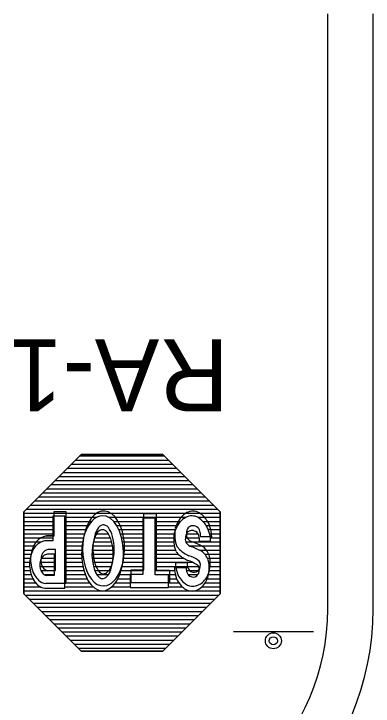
# Model space of a CAD drawing. Extents: x 1806 to 2022, y 110 to 389.
# Drawn here: x 1955.02 to 1964.59, y 293.71 to 312.13 of the extents above; entities that cross this region are included whole.
import ezdxf

# ---------------------------------------------------------------- set-up
doc = ezdxf.new("R2010")
doc.units = 0
for name, color, linetype in [('Level 10', 7, 'Continuous'), ('Level 44', 7, 'Continuous'), ('Level 50', 7, 'Continuous')]:
    doc.layers.add(name, color=color, linetype=linetype)

msp = doc.modelspace()

# ---------------------------------------------------------------- linework, layer by layer
at = {"layer": 'Level 10'}
for p, q in [((1963.38, 296.293), (1963.38, 312.134)), ((1964.59, 296.293), (1964.59, 312.134))]:
    msp.add_line(p, q, dxfattribs=at)
for radius in [7.258, 6.048]:
    msp.add_arc((1957.332, 296.293), radius, 270, 360, dxfattribs=at)
at = {"layer": 'Level 44'}
for p, q in [((1956.813, 300.408), (1955.284, 298.878)), ((1958.991, 300.408), (1956.813, 300.408)), ((1960.52, 298.878), (1958.991, 300.408)), ((1955.284, 298.878), (1955.284, 296.701)), ((1956.092, 298.239), (1956.092, 298.892)), ((1956.092, 298.892), (1956.41, 298.892)), ((1956.41, 298.892), (1956.41, 296.976)), ((1960.52, 296.701), (1960.52, 298.878)), ((1956.381, 298.765), (1956.064, 298.765)), ((1956.064, 298.765), (1956.064, 298.111)), ((1956.381, 296.848), (1956.381, 298.765)), ((1958.786, 298.709), (1958.455, 298.709)), ((1958.455, 298.709), (1958.455, 297.21)), ((1958.482, 298.836), (1958.814, 298.836)), ((1958.482, 297.337), (1958.482, 298.836)), ((1958.786, 297.201), (1958.786, 298.709)), ((1958.814, 298.836), (1958.814, 297.329)), ((1960.198, 298.596), (1960.2, 298.595)), ((1956.064, 298.111), (1955.864, 298.111)), ((1956.092, 298.239), (1955.892, 298.239)), ((1955.901, 298.234), (1956.092, 298.239)), ((1960.293, 298.217), (1959.993, 298.217)), ((1960.267, 298.09), (1959.967, 298.09)), ((1956.104, 297.751), (1955.899, 297.751)), ((1956.104, 297.751), (1955.899, 297.751)), ((1956.13, 297.877), (1955.926, 297.877)), ((1956.13, 297.877), (1955.926, 297.877)), ((1956.104, 297.193), (1956.104, 297.751)), ((1956.104, 297.193), (1956.104, 297.751)), ((1956.13, 297.32), (1956.13, 297.877)), ((1956.13, 297.32), (1956.13, 297.877)), ((1959.296, 297.402), (1959.622, 297.402)), ((1959.322, 297.529), (1959.65, 297.529)), ((1955.895, 297.193), (1956.104, 297.193)), ((1955.895, 297.193), (1956.104, 297.193)), ((1955.922, 297.32), (1956.13, 297.32)), ((1955.922, 297.32), (1956.13, 297.32)), ((1957.441, 297.235), (1957.428, 297.232)), ((1958.455, 297.21), (1958.12, 297.21)), ((1958.12, 297.21), (1958.12, 296.866)), ((1958.146, 296.994), (1958.146, 297.337)), ((1958.146, 297.337), (1958.482, 297.337)), ((1959.139, 297.201), (1958.786, 297.201)), ((1958.814, 297.329), (1959.166, 297.329)), ((1959.139, 296.866), (1959.139, 297.201)), ((1959.166, 297.329), (1959.166, 296.994)), ((1955.847, 296.848), (1956.381, 296.848)), ((1956.41, 296.976), (1955.874, 296.976)), ((1957.428, 296.909), (1957.418, 296.908)), ((1958.12, 296.866), (1959.139, 296.866)), ((1959.166, 296.994), (1958.146, 296.994)), ((1955.284, 296.701), (1956.813, 295.172)), ((1958.991, 295.172), (1960.52, 296.701)), ((1963.003, 295.688), (1960.87, 295.688)), ((1956.813, 295.172), (1958.991, 295.172))]:
    msp.add_line(p, q, dxfattribs=at)
msp.add_lwpolyline([(1955.284, 298.879), (1956.813, 300.408), (1958.991, 300.408), (1960.52, 298.879), (1960.52, 296.701), (1958.991, 295.173), (1956.813, 295.173), (1955.284, 296.701)], close=True, dxfattribs=at)
for points in [[(1959.039, 300.36), (1956.765, 300.36)], [(1959.256, 300.141), (1956.548, 300.141)], [(1959.142, 300.25), (1956.656, 300.25)], [(1959.366, 300.032), (1956.439, 300.032)], [(1959.582, 299.815), (1956.222, 299.815)], [(1959.474, 299.923), (1956.331, 299.923)], [(1959.801, 299.596), (1956.003, 299.596)], [(1959.692, 299.706), (1956.112, 299.706)], [(1959.909, 299.488), (1955.895, 299.488)], [(1960.128, 299.27), (1955.676, 299.27)], [(1960.018, 299.379), (1955.786, 299.379)], [(1960.345, 299.053), (1955.46, 299.053)], [(1960.237, 299.162), (1955.568, 299.162)], [(1960.454, 298.943), (1955.35, 298.943)], [(1960.52, 298.835), (1955.284, 298.835)], [(1956.064, 298.726), (1955.284, 298.726)], [(1957.219, 298.726), (1956.381, 298.726)], [(1959.596, 298.726), (1957.562, 298.726)], [(1960.52, 298.726), (1959.932, 298.726)], [(1956.064, 298.617), (1955.284, 298.617)], [(1956.064, 298.509), (1955.284, 298.509)], [(1957.088, 298.617), (1956.381, 298.617)], [(1957.01, 298.509), (1956.381, 298.509)], [(1958.455, 298.617), (1957.693, 298.617)], [(1958.455, 298.509), (1957.771, 298.509)], [(1959.452, 298.617), (1958.786, 298.617)], [(1959.374, 298.509), (1958.786, 298.509)], [(1960.52, 298.617), (1960.057, 298.617)], [(1960.52, 298.509), (1960.146, 298.509)], [(1956.064, 298.399), (1955.284, 298.399)], [(1956.064, 298.29), (1955.284, 298.29)], [(1956.954, 298.399), (1956.381, 298.399)], [(1956.91, 298.29), (1956.381, 298.29)], [(1957.549, 298.29), (1957.224, 298.29)], [(1958.455, 298.399), (1957.828, 298.399)], [(1958.455, 298.29), (1957.867, 298.29)], [(1959.321, 298.399), (1958.786, 298.399)], [(1959.286, 298.29), (1958.786, 298.29)], [(1959.924, 298.29), (1959.613, 298.29)], [(1960.52, 298.399), (1960.197, 298.399)], [(1960.52, 298.29), (1960.232, 298.29)], [(1956.064, 298.182), (1955.284, 298.182)], [(1956.878, 298.182), (1956.381, 298.182)], [(1957.598, 298.182), (1957.166, 298.182)], [(1958.455, 298.182), (1957.898, 298.182)], [(1959.279, 298.182), (1958.786, 298.182)], [(1959.957, 298.182), (1959.588, 298.182)], [(1960.52, 298.182), (1960.254, 298.182)], [(1955.748, 298.072), (1955.284, 298.072)], [(1955.598, 297.964), (1955.284, 297.964)], [(1956.856, 298.072), (1956.381, 298.072)], [(1956.838, 297.964), (1956.381, 297.964)], [(1957.653, 297.964), (1957.114, 297.964)], [(1957.632, 298.072), (1957.137, 298.072)], [(1958.455, 298.072), (1957.915, 298.072)], [(1958.455, 297.964), (1957.929, 297.964)], [(1959.279, 298.072), (1958.786, 298.072)], [(1959.296, 297.964), (1958.786, 297.964)], [(1960.52, 298.072), (1959.6, 298.072)], [(1960.52, 297.964), (1959.712, 297.964)], [(1955.524, 297.856), (1955.284, 297.856)], [(1955.486, 297.746), (1955.284, 297.746)], [(1956.831, 297.856), (1956.381, 297.856)], [(1956.826, 297.746), (1956.381, 297.746)], [(1957.666, 297.856), (1957.101, 297.856)], [(1957.666, 297.746), (1957.106, 297.746)], [(1958.455, 297.856), (1957.938, 297.856)], [(1958.455, 297.746), (1957.938, 297.746)], [(1959.326, 297.856), (1958.786, 297.856)], [(1959.409, 297.746), (1958.786, 297.746)], [(1960.52, 297.856), (1959.97, 297.856)], [(1960.52, 297.746), (1960.111, 297.746)], [(1955.456, 297.637), (1955.284, 297.637)], [(1956.104, 297.637), (1955.751, 297.637)], [(1956.835, 297.637), (1956.381, 297.637)], [(1957.659, 297.637), (1957.106, 297.637)], [(1958.451, 297.637), (1957.933, 297.637)], [(1959.556, 297.637), (1958.786, 297.637)], [(1960.52, 297.637), (1960.179, 297.637)], [(1955.442, 297.529), (1955.284, 297.529)], [(1955.445, 297.42), (1955.284, 297.42)], [(1956.109, 297.529), (1955.716, 297.529)], [(1956.104, 297.42), (1955.72, 297.42)], [(1956.844, 297.529), (1956.381, 297.529)], [(1956.865, 297.42), (1956.381, 297.42)], [(1957.653, 297.529), (1957.123, 297.529)], [(1957.623, 297.42), (1957.148, 297.42)], [(1958.455, 297.42), (1957.902, 297.42)], [(1958.455, 297.529), (1957.921, 297.529)], [(1959.801, 297.529), (1958.786, 297.529)], [(1959.94, 297.42), (1958.786, 297.42)], [(1960.52, 297.529), (1960.21, 297.529)], [(1960.52, 297.42), (1960.224, 297.42)], [(1955.46, 297.312), (1955.284, 297.312)], [(1955.486, 297.201), (1955.284, 297.201)], [(1956.104, 297.312), (1955.748, 297.312)], [(1956.104, 297.201), (1955.851, 297.201)], [(1956.892, 297.312), (1956.381, 297.312)], [(1956.932, 297.201), (1956.381, 297.201)], [(1957.593, 297.312), (1957.184, 297.312)], [(1957.54, 297.201), (1957.237, 297.201)], [(1958.12, 297.201), (1957.836, 297.201)], [(1958.455, 297.312), (1957.875, 297.312)], [(1959.301, 297.312), (1958.786, 297.312)], [(1959.326, 297.201), (1959.139, 297.201)], [(1959.957, 297.312), (1959.618, 297.312)], [(1959.909, 297.201), (1959.664, 297.201)], [(1960.52, 297.201), (1960.197, 297.201)], [(1960.52, 297.312), (1960.219, 297.312)], [(1955.538, 297.093), (1955.284, 297.093)], [(1956.979, 297.093), (1956.381, 297.093)], [(1958.12, 297.093), (1957.789, 297.093)], [(1959.357, 297.093), (1959.139, 297.093)], [(1960.52, 297.093), (1960.166, 297.093)], [(1955.607, 296.984), (1955.284, 296.984)], [(1955.748, 296.876), (1955.284, 296.876)], [(1957.048, 296.984), (1956.381, 296.984)], [(1957.154, 296.876), (1956.381, 296.876)], [(1958.12, 296.876), (1957.615, 296.876)], [(1958.12, 296.984), (1957.714, 296.984)], [(1959.417, 296.984), (1959.139, 296.984)], [(1959.513, 296.876), (1959.139, 296.876)], [(1960.52, 296.876), (1960.015, 296.876)], [(1960.52, 296.984), (1960.106, 296.984)], [(1960.52, 296.767), (1955.284, 296.767)], [(1960.476, 296.657), (1955.329, 296.657)], [(1960.366, 296.549), (1955.438, 296.549)], [(1960.258, 296.44), (1955.546, 296.44)], [(1960.149, 296.331), (1955.655, 296.331)], [(1960.04, 296.222), (1955.764, 296.222)], [(1959.932, 296.113), (1955.872, 296.113)], [(1959.823, 296.004), (1955.982, 296.004)], [(1959.712, 295.896), (1956.091, 295.896)], [(1959.604, 295.786), (1956.2, 295.786)], [(1959.495, 295.678), (1956.313, 295.678)], [(1959.387, 295.57), (1956.417, 295.57)], [(1959.279, 295.46), (1956.525, 295.46)], [(1959.17, 295.351), (1956.639, 295.351)], [(1959.06, 295.242), (1956.745, 295.242)]]:
    msp.add_lwpolyline(points, dxfattribs=at)
for radius in [0.213, 0.107]:
    msp.add_circle((1961.932, 295.449), radius, dxfattribs=at)
for centre, radius, start, end in [((1959.869, 298.397), 0.521, 113.1413, 144.9906), ((1959.793, 298.574), 0.326, 52.0536, 112.7397), ((1960.19, 298.182), 0.907, 145.5092, 163.2894), ((1959.842, 298.27), 0.521, 113.1413, 144.9905), ((1959.766, 298.447), 0.326, 52.0536, 112.7397), ((1959.544, 298.13), 0.713, 28.4154, 53.6553), ((1959.57, 298.257), 0.713, 28.4154, 53.6553), ((1960.163, 298.055), 0.907, 145.5092, 163.2894), ((1959.802, 298.305), 0.207, 95.4374, 134.0626), ((1959.786, 298.287), 0.223, 50.6966, 91.4573), ((1959.292, 298.173), 1.001, 2.3841, 24.9519), ((1960.434, 298.135), 1.154, 171.247, 183.9864), ((1960.461, 298.262), 1.154, 171.247, 183.9864), ((1959.865, 298.18), 0.275, 146.253, 178.7323), ((1959.828, 298.281), 0.213, 172.5761, 210.4776), ((1959.892, 298.307), 0.275, 146.253, 178.7323), ((1959.775, 298.178), 0.207, 95.4374, 134.0625), ((1959.759, 298.16), 0.223, 50.6966, 91.4573), ((1959.728, 298.181), 0.229, 6.8728, 42.7449), ((1959.755, 298.308), 0.229, 6.8728, 42.7449), ((1959.54, 298.222), 0.457, 359.0172, 13.5172), ((1959.265, 298.045), 1.001, 2.3841, 24.9519), ((1955.881, 297.899), 0.319, 115.3838, 142.6188), ((1955.976, 297.777), 0.471, 106.602, 119.8091), ((1955.855, 297.998), 0.111, 79.7909, 113.5419), ((1955.881, 298.125), 0.111, 79.7909, 113.5419), ((1960.12, 298.265), 0.815, 185.9097, 201.9865), ((1959.801, 298.154), 0.213, 172.5761, 210.4776), ((1959.835, 298.306), 0.232, 214.2083, 254.1552), ((1959.513, 298.095), 0.457, 359.0171, 13.5172), ((1956.518, 297.549), 1.058, 158.3153, 168.6699), ((1955.988, 297.624), 0.516, 138.2922, 158.6031), ((1955.988, 297.624), 0.516, 138.2922, 158.6031), ((1956.015, 297.751), 0.516, 138.2922, 158.6031), ((1956.015, 297.751), 0.516, 138.2922, 158.6031), ((1955.854, 297.772), 0.319, 115.3838, 142.6187), ((1955.949, 297.65), 0.471, 106.602, 119.8091), ((1960.093, 298.138), 0.815, 185.9097, 201.9865), ((1958.378, 297.007), 1.369, 39.479, 43.426), ((1959.808, 298.179), 0.232, 214.2083, 254.1552), ((1958.419, 294.522), 3.68, 64.4624, 68.8312), ((1958.446, 294.649), 3.681, 64.4624, 68.8312), ((1959.747, 297.551), 0.508, 20.4481, 55.1107), ((1956.491, 297.422), 1.058, 158.3153, 168.6698), ((1956.277, 297.612), 0.81, 169.7521, 182.7916), ((1956.277, 297.612), 0.81, 169.7521, 182.7916), ((1956.023, 297.633), 0.278, 146.5086, 177.0313), ((1956.023, 297.633), 0.278, 146.5086, 177.0313), ((1955.943, 297.538), 0.216, 101.9191, 145.7868), ((1955.943, 297.538), 0.216, 101.9191, 145.7868), ((1955.97, 297.665), 0.216, 101.9191, 145.7868), ((1955.97, 297.665), 0.216, 101.9191, 145.7868), ((1958.351, 296.88), 1.368, 39.479, 43.426), ((1959.952, 298.313), 0.783, 226.2465, 247.9263), ((1959.979, 298.44), 0.783, 226.2465, 247.9263), ((1959.72, 297.424), 0.508, 20.4481, 55.1107), ((1956.25, 297.485), 0.81, 169.7521, 182.7916), ((1956.25, 297.485), 0.81, 169.7521, 182.7916), ((1956.474, 297.632), 1.008, 183.3903, 195.6597), ((1955.997, 297.506), 0.278, 146.5085, 177.0313), ((1955.997, 297.506), 0.278, 146.5085, 177.0313), ((1956.053, 297.595), 0.312, 170.3417, 195.2342), ((1956.053, 297.595), 0.312, 170.3417, 195.2342), ((1959.294, 296.528), 1.12, 57.9816, 70.979), ((1959.321, 296.655), 1.12, 57.9816, 70.979), ((1959.83, 297.468), 0.161, 344.131, 58.1476), ((1959.51, 297.402), 0.714, 354.8171, 15.9183), ((1959.537, 297.529), 0.714, 354.8171, 15.9183), ((1956.447, 297.504), 1.008, 183.3903, 195.6597), ((1956.026, 297.468), 0.312, 170.3416, 195.2342), ((1956.026, 297.468), 0.312, 170.3416, 195.2342), ((1956.015, 297.43), 0.294, 188.6031, 214.217), ((1956.015, 297.43), 0.294, 188.6031, 214.217), ((1956.042, 297.557), 0.294, 188.6031, 214.217), ((1956.042, 297.557), 0.294, 188.6031, 214.217), ((1955.954, 297.501), 0.189, 215.1198, 259.3117), ((1955.954, 297.501), 0.189, 215.1198, 259.3117), ((1960.126, 297.417), 0.829, 180.6952, 197.1451), ((1960.153, 297.544), 0.829, 180.6952, 197.1452), ((1959.883, 297.362), 0.27, 170.4412, 219.3244), ((1959.91, 297.489), 0.27, 170.4412, 219.3244), ((1959.809, 297.442), 0.176, 293.8064, 352.2407), ((1959.803, 297.341), 0.161, 344.131, 58.1476), ((1959.437, 297.507), 0.813, 337.7332, 357.1392), ((1955.982, 297.351), 0.519, 193.0674, 213.762), ((1956.008, 297.478), 0.519, 193.0674, 213.762), ((1956.002, 297.431), 0.488, 209.2241, 228.5308), ((1956.002, 297.431), 0.488, 209.2241, 228.5308), ((1955.927, 297.374), 0.189, 215.1198, 259.3117), ((1955.927, 297.374), 0.189, 215.1198, 259.3117), ((1959.941, 297.449), 0.599, 194.564, 229.0063), ((1959.796, 297.329), 0.184, 227.3017, 289.0119), ((1959.823, 297.456), 0.185, 227.3017, 289.0119), ((1959.782, 297.315), 0.176, 293.8064, 352.2407), ((1959.66, 297.437), 0.58, 303.3662, 335.6734), ((1959.41, 297.38), 0.813, 337.7332, 357.1392), ((1955.975, 297.304), 0.488, 209.2241, 228.5308), ((1955.975, 297.304), 0.488, 209.2241, 228.5308), ((1955.902, 297.291), 0.318, 224.8528, 265.0441), ((1959.914, 297.322), 0.598, 194.564, 229.0063), ((1959.633, 297.31), 0.58, 303.3662, 335.6734), ((1955.876, 297.164), 0.318, 224.8528, 265.0441), ((1959.766, 297.128), 0.355, 226.1369, 301.3987), ((1959.793, 297.255), 0.355, 226.1369, 301.3987)]:
    msp.add_arc(centre, radius, start, end, dxfattribs=at)
for centre, major_axis, ratio, start_param, end_param in [((1957.41, 297.906), (0.007, 0.998), 0.558644, 4.129576, 6.939747), ((1957.41, 297.906), (0.007, 0.998), 0.558644, 0.656861, 3.168126), ((1957.384, 297.779), (0.007, 0.998), 0.558644, 3.185857, 9.451311), ((1957.41, 297.883), (-0.003, 0.652), 0.432619, 3.890436, 7.165085), ((1957.384, 297.756), (-0.003, 0.652), 0.432619, 3.239639, 9.473919), ((1957.41, 297.883), (-0.003, 0.652), 0.432619, 0.881967, 3.190734), ((1957.41, 297.883), (-0.003, 0.652), 0.432619, 3.239639, 3.888884), ((1957.41, 297.906), (0.007, 0.998), 0.558644, 3.185857, 4.129398)]:
    msp.add_ellipse(centre, major_axis=major_axis, ratio=ratio, start_param=start_param, end_param=end_param, dxfattribs=at)

# ---------------------------------------------------------------- texts
at = {"layer": 'Level 50'}
msp.add_text('RA-1', height=1.92, rotation=180, dxfattribs=at).set_placement((1960.746, 303.472))

doc.saveas('drawing.dxf')
